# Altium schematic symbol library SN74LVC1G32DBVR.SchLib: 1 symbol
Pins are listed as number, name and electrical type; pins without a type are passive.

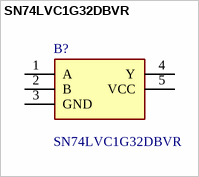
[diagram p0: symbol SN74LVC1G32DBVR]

## SN74LVC1G32DBVR
designator B?
Texas Instruments SN74LVC1G32DBVR, 2-Input OR Logic Gate, 1.65  5.5 V, 5-Pin SOT-23; Geometry.Height: 1.45mm
footprint SOT95P280X145-5N
pins: 1 A, 2 B, 3 GND, 4 Y, 5 VCC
